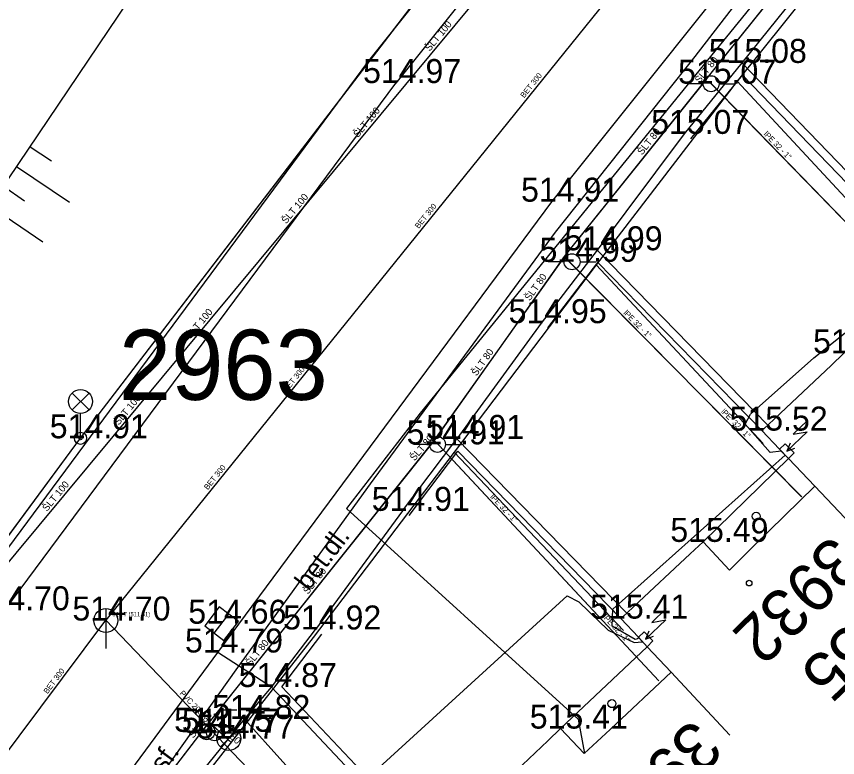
# Model space of a CAD drawing. Extents: x -668867 to -667827, y -1131943 to -1131019.
# Drawn here: x -668372.92 to -668347.24, y -1131261.67 to -1131238.49 of the extents above; entities that cross this region are included whole.
import ezdxf

# ---------------------------------------------------------------- set-up
doc = ezdxf.new("R2010")
doc.units = 0
for name, color, linetype in [('G_Bod_tecka', 7, 'Continuous'), ('G_Bod_vyska', 7, 'Continuous'), ('G_Breh_Teren', 7, 'Continuous'), ('G_Budovy-znacky', 7, 'Continuous'), ('G_Budovy_Objekty', 7, 'Continuous'), ('G_Budovy_vstupy', 7, 'Continuous'), ('G_Cesty_Schody', 7, 'Continuous'), ('G_Cisla_orientacni', 7, 'Continuous'), ('G_Cisla_popisna', 7, 'Continuous'), ('G_Objekty_technicke', 7, 'Continuous'), ('G_Plochy_zpevnene', 7, 'Continuous'), ('G_Ploty', 7, 'Continuous'), ('G_Ploty_vstupy', 7, 'Continuous'), ('G_Popisy_povrchu', 7, 'Continuous'), ('G_Site-kanalizace', 7, 'Continuous'), ('G_Site-Rozvadece', 7, 'Continuous'), ('G_Site-vodovod', 7, 'Continuous'), ('G_Vyskove_srafy', 7, 'Continuous'), ('G_Z_ELsilove_podz_kotovane', 7, 'Continuous'), ('G_Z_KANAL_podz_kotovane', 7, 'Continuous'), ('G_Z_PLYNY_podz_geodeticky', 7, 'Continuous'), ('G_Z_SPOJE_podz_geodeticky', 7, 'Continuous'), ('G_Z_SPOJE_podz_kotovane', 7, 'Continuous'), ('G_Z_SPOJE_podz_priblizne', 7, 'Continuous'), ('G_Z_VODA_podz_kotovane', 7, 'Continuous'), ('Vrstva 1', 7, 'Continuous'), ('Vrstva 13', 7, 'Continuous'), ('Vrstva 17', 7, 'Continuous'), ('Vrstva 2', 7, 'Continuous'), ('Vrstva 25', 7, 'Continuous'), ('Vrstva 27', 7, 'Continuous'), ('Vrstva 3', 7, 'Continuous'), ('Vrstva 4', 7, 'Continuous'), ('Vrstva 6', 7, 'Continuous'), ('Vrstva 7', 7, 'Continuous'), ('Vrstva 8', 7, 'Continuous')]:
    doc.layers.add(name, color=color, linetype=linetype)

msp = doc.modelspace()

# ---------------------------------------------------------------- linework, layer by layer
at = {"layer": 'G_Bod_tecka'}
for p, q in [((-668350.23, -1131239.94), (-668350.23, -1131239.94)), ((-668361.05, -1131240.57), (-668361.05, -1131240.57)), ((-668351.19, -1131240.59), (-668351.19, -1131240.59)), ((-668352.03, -1131242.16), (-668352.03, -1131242.16)), ((-668356.17, -1131244.28), (-668356.17, -1131244.28)), ((-668354.75, -1131245.8), (-668354.75, -1131245.8)), ((-668355.54, -1131246.16), (-668355.54, -1131246.16)), ((-668356.5, -1131248.08), (-668356.5, -1131248.08)), ((-668349.6, -1131251.44), (-668349.6, -1131251.44)), ((-668370.91, -1131251.68), (-668370.91, -1131251.68)), ((-668359.14, -1131251.7), (-668359.14, -1131251.7)), ((-668359.75, -1131251.87), (-668359.75, -1131251.87)), ((-668360.84, -1131253.95), (-668360.84, -1131253.95)), ((-668351.44, -1131254.92), (-668351.44, -1131254.92)), ((-668370.12, -1131257.38), (-668370.12, -1131257.38)), ((-668354.01, -1131257.32), (-668354.01, -1131257.32)), ((-668366.5, -1131257.48), (-668366.5, -1131257.48)), ((-668363.56, -1131257.66), (-668363.56, -1131257.66)), ((-668366.62, -1131258.38), (-668366.62, -1131258.38)), ((-668364.94, -1131259.46), (-668364.94, -1131259.46)), ((-668365.78, -1131260.46), (-668365.78, -1131260.46)), ((-668366.96, -1131260.86), (-668366.96, -1131260.86)), ((-668366.72, -1131260.89), (-668366.72, -1131260.89)), ((-668355.9, -1131260.76), (-668355.9, -1131260.76)), ((-668366.27, -1131261.07), (-668366.27, -1131261.07))]:
    msp.add_line(p, q, dxfattribs=at)
at = {"layer": 'G_Breh_Teren'}
msp.add_lwpolyline([(-668377.87, -1131250.54), (-668368.78, -1131237.06)], dxfattribs=at)
at = {"layer": 'G_Budovy-znacky'}
for centre, radius in [((-668349.78, -1131254.12), 0.125), ((-668350, -1131256.21), 0.0875), ((-668354.29, -1131259.98), 0.125)]:
    msp.add_circle(centre, radius, dxfattribs=at)
at = {"layer": 'G_Budovy_Objekty'}
for p, q in [((-668347.44, -1131249.4), (-668347.04, -1131249.02)), ((-668349.42, -1131251.27), (-668349.2, -1131251.06)), ((-668349.6, -1131251.44), (-668349.42, -1131251.27)), ((-668349.05, -1131252.02), (-668349.6, -1131251.44)), ((-668348.77, -1131252.31), (-668349.05, -1131252.02)), ((-668351.44, -1131254.92), (-668348.77, -1131252.31)), ((-668347.95, -1131253.18), (-668348.77, -1131252.31)), ((-668349.84, -1131255.03), (-668347.95, -1131253.18)), ((-668346.16, -1131255.07), (-668347.95, -1131253.18)), ((-668351.84, -1131255.29), (-668351.44, -1131254.92)), ((-668350.62, -1131255.8), (-668351.44, -1131254.92)), ((-668354.01, -1131257.32), (-668353.83, -1131257.15)), ((-668353.83, -1131257.15), (-668353.61, -1131256.94)), ((-668353.46, -1131257.9), (-668354.01, -1131257.32)), ((-668353.19, -1131258.2), (-668353.46, -1131257.9)), ((-668355.9, -1131260.76), (-668353.19, -1131258.2)), ((-668352.44, -1131259), (-668353.19, -1131258.2)), ((-668354.35, -1131260.79), (-668352.44, -1131259)), ((-668350.6, -1131260.97), (-668352.44, -1131259)), ((-668355.9, -1131260.76), (-668356.3, -1131261.14)), ((-668355.16, -1131261.54), (-668355.9, -1131260.76))]:
    msp.add_line(p, q, dxfattribs=at)
at = {"layer": 'G_Budovy_vstupy'}
for p, q in [((-668347.44, -1131249.4), (-668349.2, -1131251.06)), ((-668349.84, -1131255.03), (-668350.62, -1131255.8)), ((-668351.84, -1131255.29), (-668353.61, -1131256.94)), ((-668354.35, -1131260.79), (-668355.16, -1131261.54)), ((-668356.3, -1131261.14), (-668358.15, -1131262.9))]:
    msp.add_line(p, q, dxfattribs=at)
at = {"layer": 'G_Cesty_Schody'}
for points in [[(-668364.94, -1131259.46), (-668366.62, -1131258.38)], [(-668365.78, -1131260.46), (-668362.46, -1131264.17)]]:
    msp.add_lwpolyline(points, dxfattribs=at)
at = {"layer": 'G_Objekty_technicke'}
for p, q in [((-668371.175, -1131250.265), (-668370.645, -1131250.795)), ((-668371.175, -1131250.795), (-668370.645, -1131250.265)), ((-668370.91, -1131251.68), (-668370.91, -1131250.905))]:
    msp.add_line(p, q, dxfattribs=at)
for centre, radius in [((-668370.91, -1131250.53), 0.375), ((-668370.91, -1131251.68), 0.19), ((-668370.91, -1131251.68), 0.05)]:
    msp.add_circle(centre, radius, dxfattribs=at)
at = {"layer": 'G_Plochy_zpevnene'}
for p, q in [((-668356.17, -1131244.28), (-668348.64, -1131234.86)), ((-668366.62, -1131258.38), (-668356.17, -1131244.28)), ((-668370.22, -1131263.27), (-668366.62, -1131258.38))]:
    msp.add_line(p, q, dxfattribs=at)
for points in [[(-668353.43, -1131209.2), (-668352.13, -1131210.76), (-668350.41, -1131213.28), (-668348.84, -1131216.01), (-668348.38, -1131217.03), (-668347.97, -1131218.62), (-668347.92, -1131219.42), (-668347.97, -1131220.19), (-668348.43, -1131222.38), (-668348.95, -1131224.03), (-668350.02, -1131226.42), (-668350.69, -1131227.53), (-668351.44, -1131228.57), (-668356.24, -1131234.57), (-668361.05, -1131240.57)], [(-668373.28, -1131257.06), (-668361.05, -1131240.57)], [(-668365.78, -1131260.46), (-668364.94, -1131259.46)], [(-668368.35, -1131263.63), (-668365.78, -1131260.46)]]:
    msp.add_lwpolyline(points, dxfattribs=at)
at = {"layer": 'G_Ploty'}
for p, q in [((-668350.23, -1131239.94), (-668352.03, -1131242.16)), ((-668345.01, -1131245.35), (-668350.23, -1131239.94)), ((-668351.82, -1131242.31), (-668350.21, -1131240.32)), ((-668350.21, -1131240.32), (-668345.19, -1131245.52)), ((-668354.75, -1131245.8), (-668356.5, -1131248.08)), ((-668349.42, -1131251.27), (-668354.75, -1131245.8)), ((-668356.3, -1131248.23), (-668354.73, -1131246.18)), ((-668354.73, -1131246.18), (-668349.6, -1131251.44)), ((-668360.84, -1131253.95), (-668359.14, -1131251.7)), ((-668359.14, -1131251.7), (-668353.83, -1131257.15)), ((-668360.63, -1131254.1), (-668359.11, -1131252.08)), ((-668359.11, -1131252.08), (-668354.01, -1131257.32)), ((-668364.94, -1131259.46), (-668363.56, -1131257.66)), ((-668364.61, -1131259.45), (-668363.36, -1131257.81)), ((-668364.94, -1131259.46), (-668350.79, -1131274.49)), ((-668350.6, -1131274.32), (-668364.61, -1131259.45))]:
    msp.add_line(p, q, dxfattribs=at)
at = {"layer": 'G_Ploty_vstupy'}
for p, q in [((-668347.43, -1131236.46), (-668350.23, -1131239.94)), ((-668352.03, -1131242.16), (-668354.75, -1131245.8)), ((-668356.5, -1131248.08), (-668359.14, -1131251.7)), ((-668360.84, -1131253.95), (-668363.56, -1131257.66))]:
    msp.add_line(p, q, dxfattribs=at)
at = {"layer": 'G_Site-kanalizace'}
for p, q in [((-668370.12, -1131257.005), (-668370.12, -1131258.255)), ((-668366.729, -1131257.777), (-668366.272, -1131257.182))]:
    msp.add_line(p, q, dxfattribs=at)
msp.add_lwpolyline([(-668366.432, -1131258.005), (-668365.975, -1131257.41), (-668366.57, -1131256.953), (-668367.027, -1131257.548)], close=True, dxfattribs=at)
msp.add_circle((-668370.12, -1131257.38), 0.375, dxfattribs=at)
at = {"layer": 'G_Site-Rozvadece'}
for p, q in [((-668348.175, -1131251.125), (-668348.629, -1131251.556)), ((-668348.185, -1131251.479), (-668348.82, -1131252.081)), ((-668348.629, -1131251.556), (-668348.185, -1131251.479)), ((-668349.05, -1131252.02), (-668348.87, -1131251.85)), ((-668348.87, -1131251.85), (-668348.59, -1131252.14)), ((-668348.718, -1131251.833), (-668348.82, -1131252.081)), ((-668348.82, -1131252.081), (-668348.567, -1131251.992)), ((-668348.59, -1131252.14), (-668348.77, -1131252.31)), ((-668352.591, -1131257.007), (-668353.047, -1131257.437)), ((-668352.603, -1131257.361), (-668353.241, -1131257.961)), ((-668353.047, -1131257.437), (-668352.603, -1131257.361)), ((-668353.46, -1131257.9), (-668353.28, -1131257.73)), ((-668353.28, -1131257.73), (-668353.01, -1131258.02)), ((-668353.137, -1131257.713), (-668353.241, -1131257.961)), ((-668353.241, -1131257.961), (-668352.987, -1131257.873)), ((-668353.01, -1131258.02), (-668353.19, -1131258.2))]:
    msp.add_line(p, q, dxfattribs=at)
at = {"layer": 'G_Site-vodovod'}
for p, q in [((-668351.44, -1131240.59), (-668351.94, -1131240.59)), ((-668350.94, -1131240.59), (-668350.44, -1131240.59)), ((-668355.79, -1131246.16), (-668356.29, -1131246.16)), ((-668355.29, -1131246.16), (-668354.79, -1131246.16)), ((-668360, -1131251.87), (-668360.5, -1131251.87)), ((-668359.5, -1131251.87), (-668359, -1131251.87)), ((-668366.52, -1131260.17), (-668366.02, -1131260.17)), ((-668366.27, -1131260.695), (-668366.27, -1131260.17)), ((-668367.21, -1131260.86), (-668367.71, -1131260.86)), ((-668366.97, -1131260.89), (-668367.47, -1131260.89)), ((-668366.71, -1131260.86), (-668366.21, -1131260.86)), ((-668366.535, -1131261.335), (-668366.005, -1131260.805)), ((-668366.47, -1131260.89), (-668365.97, -1131260.89))]:
    msp.add_line(p, q, dxfattribs=at)
for centre, radius in [((-668351.19, -1131240.59), 0.25), ((-668355.54, -1131246.16), 0.25), ((-668359.75, -1131251.87), 0.25), ((-668366.96, -1131260.86), 0.25), ((-668366.72, -1131260.89), 0.25), ((-668366.27, -1131261.07), 0.375)]:
    msp.add_circle(centre, radius, dxfattribs=at)
at = {"layer": 'G_Vyskove_srafy'}
for points in [[(-668372.49, -1131242.56), (-668371.82, -1131243)], [(-668372.91, -1131243.18), (-668371.25, -1131244.3)], [(-668373.32, -1131243.8), (-668372.66, -1131244.25)], [(-668373.74, -1131244.42), (-668372.09, -1131245.54)]]:
    msp.add_lwpolyline(points, dxfattribs=at)
at = {"layer": 'G_Z_ELsilove_podz_kotovane'}
for points in [[(-668413.74, -1131320.95), (-668412.29, -1131319.3), (-668403.95, -1131313.7), (-668402.11, -1131310.49), (-668408.44, -1131302.38), (-668406.24, -1131299.85), (-668388.22, -1131275.11), (-668370.91, -1131251.68), (-668351.39, -1131226.2), (-668349.57, -1131222.57), (-668349.25, -1131218.16), (-668350.22, -1131215.68), (-668344.03, -1131209.01), (-668341.17, -1131210.62), (-668339.446, -1131210.257)], [(-668369.137, -1131263.277), (-668365.995, -1131258.854), (-668361.842, -1131253.109), (-668356.055, -1131245.238), (-668351.685, -1131239.744), (-668350.135, -1131237.714)], [(-668366.983, -1131266.922), (-668355.691, -1131256.61), (-668355.33, -1131256.794), (-668354.406, -1131257.68), (-668353.597, -1131258.063), (-668353.476, -1131258.058), (-668353.333, -1131258.044), (-668353.451, -1131257.919), (-668353.492, -1131257.952), (-668353.569, -1131257.971), (-668354.284, -1131257.555), (-668354.259, -1131257.026), (-668348.873, -1131252.207), (-668349.002, -1131252.082), (-668349.341, -1131252.121), (-668350.126, -1131251.24), (-668349.963, -1131250.923), (-668347.981, -1131249.162), (-668344.44, -1131246.336)]]:
    msp.add_lwpolyline(points, dxfattribs=at)
at = {"layer": 'G_Z_KANAL_podz_kotovane'}
msp.add_line((-668391.55, -1131286), (-668370.12, -1131257.37), dxfattribs=at)
for points in [[(-668345.87, -1131227.33), (-668345.87, -1131227.33), (-668370.12, -1131257.37)], [(-668370.12, -1131257.37), (-668352.13, -1131276.17), (-668350.02, -1131278.39)]]:
    msp.add_lwpolyline(points, dxfattribs=at)
at = {"layer": 'G_Z_PLYNY_podz_geodeticky'}
for points in [[(-668337.427, -1131211.521), (-668350.47, -1131225.57), (-668355.06, -1131231.31), (-668361.9, -1131239.88), (-668407.57, -1131301.56)], [(-668329.849, -1131216.265), (-668331.65, -1131218.17), (-668336.59, -1131223.38), (-668341.4, -1131229.35), (-668345.77, -1131234.76), (-668350.37, -1131240.51), (-668354.78, -1131246.26), (-668359.23, -1131252.11), (-668363.64, -1131257.91), (-668367.21, -1131262.48), (-668373.55, -1131270.81), (-668377.88, -1131276.49), (-668382.55, -1131282.62), (-668386.72, -1131288.1), (-668391.28, -1131294.08), (-668395.49, -1131299.61), (-668401.06, -1131306.92), (-668401.78, -1131307.86)], [(-668350.37, -1131240.51), (-668346.05, -1131245.17)], [(-668354.78, -1131246.26), (-668349.56, -1131251.84)], [(-668359.23, -1131252.11), (-668353.93, -1131257.69)]]:
    msp.add_lwpolyline(points, dxfattribs=at)
at = {"layer": 'G_Z_SPOJE_podz_geodeticky'}
msp.add_lwpolyline([(-668370.56, -1131213.04), (-668362.1, -1131221.69), (-668358.37, -1131223.35), (-668346.46, -1131222.21), (-668338.5, -1131221.46), (-668336.16, -1131221.23), (-668360.29, -1131250.89), (-668362.59, -1131253.88), (-668355.35, -1131260.46), (-668355.15, -1131261.54)], dxfattribs=at)
at = {"layer": 'G_Z_SPOJE_podz_kotovane'}
msp.add_lwpolyline([(-668370.56, -1131213.04), (-668362.1, -1131221.69), (-668358.37, -1131223.35), (-668346.46, -1131222.21), (-668338.5, -1131221.46), (-668336.16, -1131221.23), (-668360.29, -1131250.89), (-668362.59, -1131253.88), (-668355.35, -1131260.46), (-668355.15, -1131261.54)], dxfattribs=at)
at = {"layer": 'G_Z_SPOJE_podz_priblizne'}
msp.add_lwpolyline([(-668370.56, -1131213.04), (-668362.1, -1131221.69), (-668358.37, -1131223.35), (-668346.46, -1131222.21), (-668338.5, -1131221.46), (-668336.16, -1131221.23), (-668360.29, -1131250.89), (-668362.59, -1131253.88), (-668355.35, -1131260.46), (-668355.15, -1131261.54)], dxfattribs=at)
at = {"layer": 'G_Z_VODA_podz_kotovane'}
for points in [[(-668338.17, -1131213.47), (-668351.36, -1131229.33), (-668353.35, -1131231.71), (-668353.37, -1131231.75), (-668354.63, -1131233.25), (-668385.18, -1131269.99), (-668391.31, -1131277.36), (-668413.4, -1131303.06)], [(-668330.528, -1131215.84), (-668331.91, -1131217.26), (-668331.96, -1131217.31), (-668336.96, -1131222.75), (-668338.35, -1131224.25), (-668342.33, -1131228.98), (-668346.7, -1131234.65), (-668346.77, -1131234.74), (-668351.28, -1131240.37), (-668351.39, -1131240.51), (-668355.71, -1131245.9), (-668355.78, -1131246), (-668359.86, -1131251.75), (-668366.89, -1131260.56), (-668367.08, -1131260.8)], [(-668351.39, -1131240.51), (-668351.21, -1131240.57), (-668344.13, -1131247.85)], [(-668355.78, -1131246), (-668355.51, -1131246.27), (-668348.36, -1131253.51)], [(-668359.86, -1131251.75), (-668359.7, -1131251.9), (-668352.82, -1131259.27)], [(-668366.89, -1131260.56), (-668366.54, -1131260.88), (-668366.19, -1131261.21)], [(-668367.08, -1131260.8), (-668367.09, -1131260.81), (-668374.43, -1131270.37), (-668375.17, -1131271.33), (-668375.25, -1131271.44), (-668379.57, -1131277.34), (-668383.56, -1131282.79), (-668383.56, -1131282.79), (-668388.23, -1131289.05), (-668388.25, -1131289.08), (-668392.31, -1131294.78), (-668396, -1131299.93), (-668396.03, -1131299.97), (-668400.83, -1131306.08), (-668400.94, -1131306.24), (-668400.99, -1131306.3), (-668406.72, -1131313.47), (-668406.73, -1131313.49), (-668407.08, -1131313.88)]]:
    msp.add_lwpolyline(points, dxfattribs=at)
at = {"layer": 'Vrstva 1'}
msp.add_line((-668370.91, -1131251.68), (-668370.91, -1131251.68), dxfattribs=at)
at = {"layer": 'Vrstva 13'}
msp.add_line((-668391.55, -1131286), (-668370.12, -1131257.37), dxfattribs=at)
for points in [[(-668345.867, -1131227.326), (-668345.87, -1131227.33), (-668370.12, -1131257.37)], [(-668370.12, -1131257.37), (-668352.13, -1131276.17), (-668350.02, -1131278.39)]]:
    msp.add_lwpolyline(points, dxfattribs=at)
at = {"layer": 'Vrstva 17'}
for p, q in [((-668370.91, -1131251.68), (-668351.39, -1131226.2)), ((-668388.22, -1131275.11), (-668370.91, -1131251.68))]:
    msp.add_line(p, q, dxfattribs=at)
at = {"layer": 'Vrstva 25'}
for points in [[(-668351.395, -1131240.509), (-668351.213, -1131240.568), (-668344.135, -1131247.85)], [(-668355.784, -1131246), (-668355.515, -1131246.272), (-668348.356, -1131253.514)], [(-668359.856, -1131251.751), (-668359.698, -1131251.905), (-668352.82, -1131259.267)], [(-668366.89, -1131260.561), (-668366.538, -1131260.885), (-668366.186, -1131261.206)]]:
    msp.add_lwpolyline(points, dxfattribs=at)
at = {"layer": 'Vrstva 27'}
for points in [[(-668338.172, -1131213.47), (-668351.363, -1131229.328), (-668353.348, -1131231.715), (-668353.374, -1131231.746), (-668354.633, -1131233.247), (-668385.183, -1131269.991), (-668391.313, -1131277.364), (-668413.397, -1131303.063)], [(-668330.531, -1131215.838), (-668331.914, -1131217.26), (-668331.961, -1131217.313), (-668336.959, -1131222.746), (-668338.346, -1131224.254), (-668342.334, -1131228.977), (-668346.701, -1131234.655), (-668346.77, -1131234.741), (-668351.281, -1131240.367), (-668351.395, -1131240.509), (-668355.714, -1131245.901), (-668355.784, -1131246), (-668359.856, -1131251.751), (-668366.89, -1131260.561), (-668367.082, -1131260.801)], [(-668367.082, -1131260.801), (-668367.088, -1131260.809), (-668374.429, -1131270.367), (-668375.17, -1131271.332), (-668375.25, -1131271.442), (-668379.568, -1131277.339), (-668383.56, -1131282.79), (-668383.562, -1131282.793), (-668388.23, -1131289.054), (-668388.251, -1131289.082), (-668392.309, -1131294.781), (-668396.001, -1131299.93), (-668396.033, -1131299.969), (-668400.834, -1131306.083), (-668400.938, -1131306.237), (-668400.992, -1131306.302), (-668406.715, -1131313.472), (-668406.726, -1131313.486), (-668407.083, -1131313.882)]]:
    msp.add_lwpolyline(points, dxfattribs=at)
at = {"layer": 'Vrstva 6'}
for p, q in [((-668351.213, -1131240.568), (-668351.213, -1131240.568)), ((-668355.515, -1131246.272), (-668355.515, -1131246.272)), ((-668359.698, -1131251.905), (-668359.698, -1131251.905)), ((-668367.082, -1131260.801), (-668367.082, -1131260.801)), ((-668366.538, -1131260.885), (-668366.538, -1131260.885))]:
    msp.add_line(p, q, dxfattribs=at)
at = {"layer": 'Vrstva 7'}
msp.add_line((-668366.186, -1131261.206), (-668366.186, -1131261.206), dxfattribs=at)
at = {"layer": 'Vrstva 8'}
msp.add_line((-668370.12, -1131257.37), (-668370.12, -1131257.37), dxfattribs=at)

# ---------------------------------------------------------------- texts
at = {"layer": 'G_Bod_vyska'}
for s, p in [('515.08', (-668351.264, -1131239.94)), ('514.97', (-668362.074, -1131240.57)), ('515.07', (-668352.224, -1131240.59)), ('515.07', (-668353.064, -1131242.16)), ('514.91', (-668357.133, -1131244.28)), ('514.99', (-668355.776, -1131245.8)), ('514.99', (-668356.556, -1131246.16)), ('514.95', (-668357.524, -1131248.08)), ('515.81', (-668348.001, -1131249.02)), ('515.52', (-668350.612, -1131251.44)), ('514.91', (-668371.873, -1131251.68)), ('514.91', (-668360.103, -1131251.7)), ('514.91', (-668360.713, -1131251.87)), ('514.91', (-668361.803, -1131253.95)), ('515.49', (-668352.464, -1131254.92)), ('514.70', (-668374.314, -1131257.06)), ('514.70', (-668371.164, -1131257.38)), ('515.41', (-668354.971, -1131257.32)), ('514.66', (-668367.54, -1131257.48)), ('514.92', (-668364.574, -1131257.66)), ('514.79', (-668367.644, -1131258.38)), ('514.87', (-668365.962, -1131259.46)), ('514.82', (-668366.792, -1131260.46)), ('514.75', (-668367.982, -1131260.86)), ('514.77', (-668367.742, -1131260.89)), ('515.41', (-668356.861, -1131260.76)), ('514.77', (-668367.292, -1131261.07))]:
    msp.add_text(s, height=0.75, dxfattribs=at).set_placement(p)
at = {"layer": 'G_Cisla_orientacni'}
msp.add_text('55', height=1.5, rotation=224.2938, dxfattribs=at).set_placement((-668346.886, -1131257.39))
at = {"layer": 'G_Cisla_popisna'}
for s, rotation, p in [('3932', 224.2938, (-668347.408, -1131254.655)), ('3933', 223.0805, (-668351.749, -1131260.407))]:
    msp.add_text(s, height=1.5, rotation=rotation, dxfattribs=at).set_placement(p)
at = {"layer": 'G_Popisy_povrchu'}
for s, rotation, p in [('bet.dl.', 52.7863, (-668363.779, -1131256.479)), ('asf.', 53.6528, (-668368.562, -1131262.531))]:
    msp.add_text(s, height=0.6, rotation=rotation, dxfattribs=at).set_placement(p)
at = {"layer": 'Vrstva 2'}
msp.add_text('514.7 (511.61)', height=0.13163, dxfattribs=at).set_placement((-668369.914, -1131257.248))
at = {"layer": 'Vrstva 3'}
for s, rotation, p in [('BET 300', 51.0842, (-668357.038, -1131241.051)), ('BET 300', 51.0684, (-668360.336, -1131245.137)), ('BET 300', 51.1056, (-668364.458, -1131250.244)), ('BET 300', 51.0842, (-668366.931, -1131253.308)), ('BET 300', 53.2018, (-668371.943, -1131259.688)), ('PVC 200', 313.7259, (-668367.823, -1131259.67))]:
    msp.add_text(s, height=0.1755, rotation=rotation, dxfattribs=at).set_placement(p)
at = {"layer": 'Vrstva 4'}
for s, height, rotation, p in [('ŠLT 100', 0.2194, 50.2605, (-668359.991, -1131239.593)), ('ŠLT 80', 0.2194, 51.319, (-668351.55, -1131240.592)), ('ŠLT 100', 0.2194, 50.2734, (-668362.235, -1131242.292)), ('ŠLT 80', 0.2194, 51.319, (-668353.349, -1131242.838)), ('lPE 32 - 1"', 0.17551, 314.1824, (-668349.56, -1131242.18)), ('ŠLT 100', 0.2194, 50.2422, (-668364.48, -1131244.99)), ('ŠLT 80', 0.2194, 54.7269, (-668356.861, -1131247.399)), ('ŠLT 100', 0.2194, 50.2422, (-668367.472, -1131248.588)), ('lPE 32 - 1"', 0.17551, 314.6862, (-668353.945, -1131247.773)), ('ŠLT 80', 0.2194, 54.6599, (-668358.524, -1131249.748)), ('ŠLT 100', 0.2194, 50.2734, (-668369.716, -1131251.286)), ('lPE  32 - 1"', 0.17551, 314.6766, (-668350.893, -1131250.859)), ('ŠLT 80', 0.2194, 49.2812, (-668360.467, -1131252.405)), ('ŠLT 100', 0.2194, 50.2605, (-668371.96, -1131253.985)), ('lPE 32 - 1"', 0.17551, 313.1365, (-668358.112, -1131253.524)), ('ŠLT 80', 0.2194, 51.4145, (-668363.798, -1131256.575)), ('lPE 32 - 1"', 0.17551, 313.1365, (-668354.594, -1131257.282)), ('ŠLT 80', 0.2194, 51.4145, (-668365.594, -1131258.824)), ('ŠLT 80', 0.2194, 52.3858, (-668367.383, -1131261.078)), ('LT 80', 0.2194, 317.5435, (-668366.571, -1131260.758))]:
    msp.add_text(s, height=height, rotation=rotation, dxfattribs=at).set_placement(p)
msp.add_text('2963', height=2.1939, dxfattribs=at).set_placement((-668369.707, -1131250.479))

doc.saveas('drawing.dxf')
